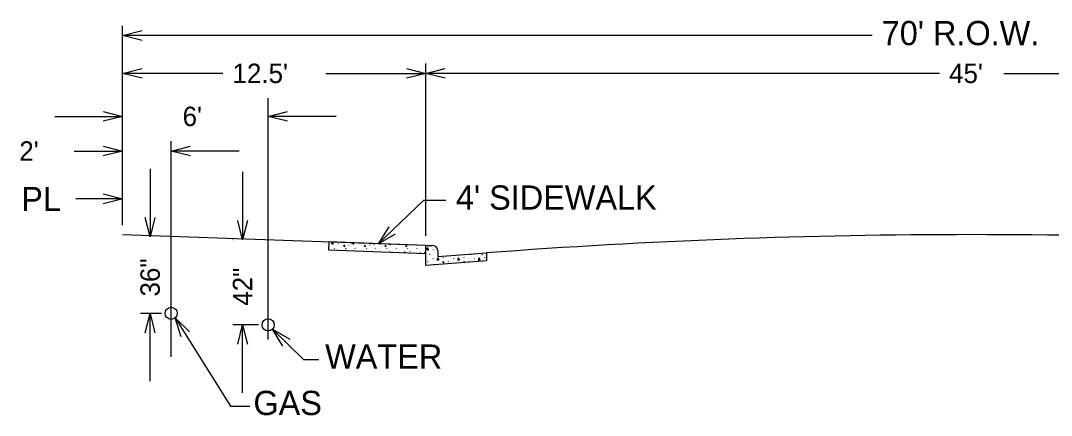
# Model space of a CAD drawing. Extents: x 524397 to 525117, y 3701341 to 3701821.
# Drawn here: x 524713.7 to 524798.7, y 3701462.4 to 3701495 of the extents above; entities that cross this region are included whole.
import ezdxf

# ---------------------------------------------------------------- set-up
doc = ezdxf.new("R2010")
doc.units = 0
doc.layers.add('Level 11', color=7, linetype='Continuous')

msp = doc.modelspace()

# ---------------------------------------------------------------- linework, layer by layer
at = {"layer": 'Level 11'}
for p, q in [((524722.143, 3701478.123), (524722.143, 3701494.575)), ((524722.143, 3701493.774), (524723.744, 3701494.175)), ((524783.936, 3701493.774), (524722.143, 3701493.774)), ((524723.744, 3701493.374), (524722.143, 3701493.774)), ((524722.143, 3701478.123), (524722.143, 3701491.449)), ((524747.143, 3701477.25), (524747.143, 3701491.449)), ((524722.143, 3701490.649), (524723.744, 3701491.049)), ((524730.401, 3701490.649), (524722.143, 3701490.649)), ((524723.744, 3701490.249), (524722.143, 3701490.649)), ((524738.885, 3701490.649), (524747.143, 3701490.649)), ((524745.542, 3701491.049), (524747.143, 3701490.649)), ((524747.143, 3701490.649), (524745.542, 3701490.249)), ((524747.143, 3701490.649), (524748.744, 3701491.049)), ((524789.489, 3701490.649), (524747.143, 3701490.649)), ((524748.744, 3701490.249), (524747.143, 3701490.649)), ((524794.796, 3701490.649), (524837.143, 3701490.649)), ((524734.143, 3701468.669), (524734.143, 3701488.606)), ((524716.539, 3701487.098), (524722.143, 3701487.098)), ((524720.542, 3701487.498), (524722.143, 3701487.098)), ((524722.143, 3701487.098), (524720.542, 3701486.698)), ((524734.143, 3701487.098), (524735.744, 3701487.498)), ((524739.746, 3701487.098), (524734.143, 3701487.098)), ((524735.744, 3701486.698), (524734.143, 3701487.098)), ((524720.542, 3701484.636), (524722.143, 3701484.236)), ((524726.143, 3701467.254), (524726.143, 3701485.05)), ((524726.143, 3701484.236), (524727.744, 3701484.636)), ((524718.14, 3701484.236), (524722.143, 3701484.236)), ((524722.143, 3701484.236), (524720.542, 3701483.836)), ((524731.746, 3701484.236), (524726.143, 3701484.236)), ((524727.744, 3701483.836), (524726.143, 3701484.236)), ((524724.405, 3701482.762), (524724.405, 3701477.158)), ((524732.031, 3701482.51), (524732.031, 3701476.906)), ((524722.148, 3701480.291), (524718.272, 3701480.291)), ((524720.547, 3701480.692), (524722.148, 3701480.291)), ((524722.148, 3701480.291), (524720.547, 3701479.891)), ((524743.204, 3701476.576), (524746.982, 3701480.187)), ((524746.982, 3701480.187), (524748.787, 3701480.187)), ((524724.405, 3701477.158), (524724.005, 3701478.759)), ((524724.806, 3701478.759), (524724.405, 3701477.158)), ((524732.031, 3701476.906), (524731.631, 3701478.507)), ((524732.431, 3701478.507), (524732.031, 3701476.906)), ((524744.085, 3701477.971), (524743.204, 3701476.576)), ((524747.143, 3701476.449), (524722.143, 3701477.322)), ((524723.628, 3701477.158), (524723.605, 3701477.158)), ((524731.255, 3701476.906), (524731.23, 3701476.906)), ((524743.204, 3701476.576), (524744.638, 3701477.393)), ((524739.148, 3701476.728), (524739.124, 3701476.069)), ((524739.124, 3701476.069), (524747.143, 3701475.789)), ((524747.143, 3701476.449), (524739.148, 3701476.728)), ((524739.611, 3701476.183), (524739.597, 3701476.215)), ((524739.935, 3701476.595), (524739.92, 3701476.627)), ((524740.535, 3701476.175), (524740.521, 3701476.154)), ((524740.549, 3701476.183), (524740.535, 3701476.162)), ((524740.792, 3701476.506), (524740.788, 3701476.474)), ((524741.313, 3701476.183), (524741.299, 3701476.215)), ((524741.636, 3701476.595), (524741.622, 3701476.627)), ((524742.236, 3701476.175), (524742.222, 3701476.154)), ((524742.251, 3701476.183), (524742.236, 3701476.162)), ((524742.493, 3701476.506), (524742.49, 3701476.474)), ((524743.014, 3701476.183), (524743, 3701476.215)), ((524743.938, 3701476.175), (524743.924, 3701476.154)), ((524743.952, 3701476.183), (524743.938, 3701476.162)), ((524744.195, 3701476.506), (524744.191, 3701476.474)), ((524744.716, 3701476.183), (524744.702, 3701476.215)), ((524745.639, 3701476.175), (524745.625, 3701476.154)), ((524745.654, 3701476.183), (524745.639, 3701476.162)), ((524745.895, 3701476.493), (524745.893, 3701476.474)), ((524746.417, 3701476.183), (524746.403, 3701476.215)), ((524747.143, 3701474.787), (524747.143, 3701476.449)), ((524747.143, 3701476.449), (524747.656, 3701476.449)), ((524747.143, 3701475.789), (524747.143, 3701476.449)), ((524747.656, 3701476.449), (524747.643, 3701476.449)), ((524747.785, 3701476.09), (524747.771, 3701476.122)), ((524744.162, 3701475.92), (524744.148, 3701475.952)), ((524744.992, 3701475.864), (524744.989, 3701475.87)), ((524745.863, 3701475.92), (524745.849, 3701475.952)), ((524746.705, 3701475.838), (524746.691, 3701475.87)), ((524747.462, 3701475.678), (524747.448, 3701475.71)), ((524747.75, 3701475.333), (524747.735, 3701475.365)), ((524748.143, 3701475.987), (524748.143, 3701475.524)), ((524748.143, 3701475.524), (524752.143, 3701475.826)), ((524748.609, 3701475.415), (524748.595, 3701475.447)), ((524749.451, 3701475.333), (524749.437, 3701475.365)), ((524750.087, 3701475.67), (524750.073, 3701475.649)), ((524750.097, 3701475.672), (524750.087, 3701475.657)), ((524750.311, 3701475.415), (524750.296, 3701475.447)), ((524750.865, 3701475.678), (524750.851, 3701475.71)), ((524751.153, 3701475.333), (524751.138, 3701475.365)), ((524751.788, 3701475.67), (524751.774, 3701475.649)), ((524751.803, 3701475.678), (524751.788, 3701475.657)), ((524752.012, 3701475.415), (524751.998, 3701475.447)), ((524752.143, 3701475.826), (524752.143, 3701475.165)), ((524752.143, 3701475.165), (524747.143, 3701474.787)), ((524747.306, 3701475.106), (524747.291, 3701475.084)), ((524749.007, 3701475.106), (524748.993, 3701475.084)), ((524750.709, 3701475.106), (524750.694, 3701475.084)), ((524725.342, 3701470.838), (524723.605, 3701470.838)), ((524724.005, 3701469.237), (524724.405, 3701470.838)), ((524724.405, 3701465.234), (524724.405, 3701470.838)), ((524724.405, 3701470.838), (524724.806, 3701469.237)), ((524726.979, 3701468.889), (524726.467, 3701470.458)), ((524726.467, 3701470.458), (524727.657, 3701469.314)), ((524726.467, 3701470.458), (524731.027, 3701463.188)), ((524733.342, 3701469.894), (524731.23, 3701469.894)), ((524731.631, 3701468.293), (524732.031, 3701469.894)), ((524732.031, 3701464.29), (524732.031, 3701469.894)), ((524732.031, 3701469.894), (524732.431, 3701468.293)), ((524735.364, 3701468.137), (524734.496, 3701469.541)), ((524734.496, 3701469.541), (524735.922, 3701468.71)), ((524734.496, 3701469.541), (524737.061, 3701467.042)), ((524737.061, 3701467.042), (524738.307, 3701467.042)), ((524731.027, 3701463.188), (524732.617, 3701463.188))]:
    msp.add_line(p, q, dxfattribs=at)
for points in [[(524739.433, 3701476.718), (524739.347, 3701476.63), (524739.499, 3701476.56)], [(524739.502, 3701476.558), (524739.481, 3701476.717)], [(524740.467, 3701476.368), (524740.425, 3701476.457), (524740.354, 3701476.403), (524740.467, 3701476.368)], [(524741.078, 3701476.661), (524741.049, 3701476.63), (524741.201, 3701476.56)], [(524741.204, 3701476.558), (524741.19, 3701476.657)], [(524742.169, 3701476.368), (524742.126, 3701476.457), (524742.055, 3701476.403), (524742.169, 3701476.368)], [(524742.815, 3701476.6), (524742.902, 3701476.56)], [(524742.905, 3701476.558), (524742.9, 3701476.597)], [(524743.87, 3701476.368), (524743.828, 3701476.457), (524743.757, 3701476.403), (524743.87, 3701476.368)], [(524745.572, 3701476.368), (524745.529, 3701476.457), (524745.458, 3701476.403), (524745.572, 3701476.368)], [(524747.353, 3701476.053), (524747.325, 3701476.256), (524747.198, 3701476.125), (524747.35, 3701476.054)], [(524743.693, 3701475.909), (524743.686, 3701475.923), (524743.68, 3701475.91)], [(524745.427, 3701475.849), (524745.387, 3701475.923), (524745.355, 3701475.851)], [(524747.143, 3701475.821), (524747.089, 3701475.923), (524747.03, 3701475.793)], [(524748.229, 3701475.237), (524748.133, 3701475.418), (524748.059, 3701475.251), (524748.225, 3701475.237)], [(524749.931, 3701475.237), (524749.835, 3701475.418), (524749.76, 3701475.251), (524749.927, 3701475.237)], [(524751.632, 3701475.237), (524751.536, 3701475.418), (524751.462, 3701475.251), (524751.628, 3701475.237)], [(524747.818, 3701474.838), (524747.813, 3701474.848), (524747.797, 3701474.837)], [(524748.634, 3701475.013), (524748.591, 3701475.102), (524748.52, 3701475.049), (524748.634, 3701475.013)], [(524750.329, 3701475.028), (524750.293, 3701475.102), (524750.222, 3701475.049), (524750.297, 3701475.025)]]:
    msp.add_lwpolyline(points, dxfattribs=at)
for centre in [(524726.143, 3701470.838), (524734.143, 3701469.894)]:
    msp.add_circle(centre, 0.5, dxfattribs=at)
for centre, radius, start, end in [((524792.143, 3700946.025), 531.309, 85.68236, 94.31764), ((524747.649, 3701475.955), 0.494, 3.70795, 90.76675)]:
    msp.add_arc(centre, radius, start, end, dxfattribs=at)

# ---------------------------------------------------------------- texts
for s, height, p in [("70' R.O.W.", 2, (524784.737, 3701492.974)), ("12.5'", 1.601, (524731.201, 3701489.848)), ("45'", 1.601, (524790.29, 3701489.848)), ("6'", 1.601, (524727.084, 3701486.297)), ("2'", 1.601, (524713.621, 3701483.435)), ('PL', 2, (524713.781, 3701479.273)), ("4' SIDEWALK", 2, (524749.624, 3701479.397)), ('WATER', 2, (524738.84, 3701466.269)), ('GAS', 2, (524732.926, 3701462.442))]:
    msp.add_text(s, height=height, dxfattribs=at).set_placement(p)
for s, p in [('36"', (524725.206, 3701472.229)), ('42"', (524732.831, 3701471.468))]:
    msp.add_text(s, height=1.601, rotation=90, dxfattribs=at).set_placement(p)

doc.saveas('drawing.dxf')
